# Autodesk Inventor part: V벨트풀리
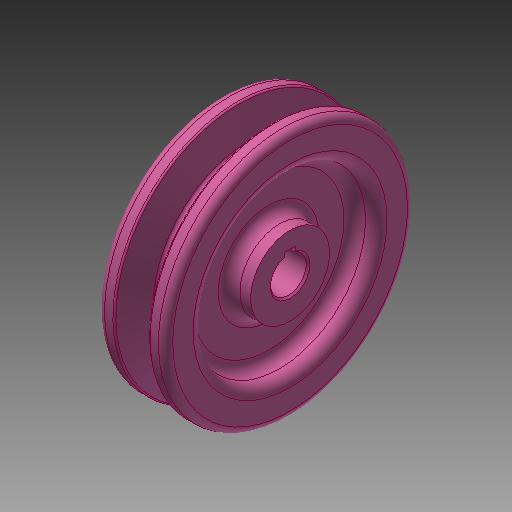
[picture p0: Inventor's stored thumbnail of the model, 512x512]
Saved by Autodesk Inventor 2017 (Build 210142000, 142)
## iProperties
Created: 2015-11
Part Number: V벨트풀리
Material: 강철, 탄소
Document SubType Name: Modeling
Designer: mduedu
Density: 1 g/cm^3
Appearance: 분홍색
Author: mduedu
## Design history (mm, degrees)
sketch "스케치1"
  geometry: L1 (-9.5, 0)-(9.5, 0); L2 (0, 0)-(0, 34.7); L3 (-4.825, 34.7)-(-9.5, 34.7); L4 (-9.5, 34.7)-(-9.5, 0); L5 (0, 25.7)-(-2.074, 25.7); L6 (-2.074, 25.7)-(-4.825, 34.7); L7 (4.825, 34.7)-(9.5, 34.7); L8 (9.5, 34.7)-(9.5, 0); L9 (0, 25.7)-(2.074, 25.7); L10 (2.074, 25.7)-(4.825, 34.7); L11 (-9.5, 32)-(9.5, 32); 3 further points
  constraints: 22 end point, 7 point on line, 4 perpendicular, 3 symmetric about line, 1 coincident, 1 horizontal, 1 horizontal alignment, 1 midpoint, 1 vertical
  dimensions: "d0" = 19 distance of L1.start L1.end; "d2" = 69.4 diameter of L2.end L1 (derived); "d3" = 34 deg angle of L10 L6; "d4" = 6.3 distance between parallel lines of L11 L9; "d5" = 2.7 distance between parallel lines of L7 L11; "d6" = 8 distance of point (4, 32) point (-4, 32); "d7" = 64 diameter of L11 L1
revolve "회전1" sketch "스케치1" stored, may be unused: angle "d8" = 90 deg
sketch "스케치2"
  geometry: C1 r 24 at (0, 0); C2 r 11 at (0, 0); 1 further point
  constraints: 2 centre point, 2 coincident
  dimensions: "d9" = 48 diameter of C1; "d10" = 22 diameter of C2
extrude "돌출1" cut sketch "스케치2" distance "d11" = 6; taper "d12" = 0 deg
fillet "모깎기1" dims "d13" = 3
fillet "모깎기2" dims "d14" = 3
fillet "모깎기3" dims "d15" = 1, "d16" = 0.5, "d17" = 2
hole "구멍1" diameter "d20" = 10; stored, may be unused: countersink angle "d24" = 90 deg, drill point angle "d26" = 118 deg; dims "d18" = 10, "d19" = 10, "d21" = 6, "d22" = 4, "d23" = 2, "d25" = 8
sketch "스케치3"
  geometry: L1 (-1.5, 0)-(1.5, 0); L2 (1.5, 0)-(1.5, 6.4); L3 (1.5, 6.4)-(-1.5, 6.4); L4 (-1.5, 6.4)-(-1.5, 0); 2 further points
  constraints: 8 end point, 2 parallel, 1 coincident, 1 horizontal, 1 midpoint, 1 perpendicular
  dimensions: "d27" = 3 distance of L2.end L3.end; "d29" = 6.4 distance of L3.end L1.start
extrude "돌출2" cut sketch "스케치3" stored distance "d30" = 6; taper "d31" = 0 deg
chamfer "모따기1" distance "d32" = 0.5; stored, may be unused: second distance "d33" = 2, angle "d34" = 45 deg
node "솔리드1"
mirror "대칭1"
